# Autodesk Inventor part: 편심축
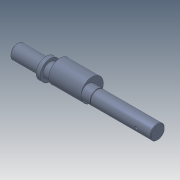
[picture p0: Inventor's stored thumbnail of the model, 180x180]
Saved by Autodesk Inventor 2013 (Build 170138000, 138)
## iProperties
Manager: 한국ATC센터
Company: 한국ATC센터
Created: 2014-10
Part Number: 편심축
Document SubType Name: Modeling
Designer: 한국ATC센터
Density: 7.86 g/cm^3
Material: 강철, 연강
Mass: 1459.35 g
Surface Area: 294.4 cm^2
Volume: 185.668 cm^3
Author: KYOUNG IL JANG
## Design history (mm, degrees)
sketch "스케치1"
  geometry: L1 (-147, 0)-(147, 0); L2 (-147, 0)-(-147, 12.5); L3 (-147, 12.5)-(-47, 12.5); L4 (-47, 12.5)-(-47, 17.5); L5 (-47, 17.5)-(-40, 17.5); L6 (-40, 17.5)-(-40, 12.5); L7 (-40, 12.5)-(41.65, 12.5); L8 (41.65, 12.5)-(41.65, 11.95); L9 (41.65, 11.95)-(43, 11.95); L10 (43, 11.95)-(43, 12.5); L11 (43, 12.5)-(147, 12.5); L12 (147, 12.5)-(147, 0); L13 (114, 12.5)-(114, 9.1); L14 (114, 9.1)-(139, 9.1); L15 (139, 9.1)-(139, 12.5); L16 (122, -12.5)-(124.5, -12.5); L17 (124.5, -12.5)-(122, -10); L18 (122, -10)-(122, -12.5); L19 (-114, 12.5)-(-114, 9.1); L20 (-114, 9.1)-(-139, 9.1); L21 (-139, 9.1)-(-139, 12.5); L22 (-122, -12.5)-(-122, -10); L23 (-122, -10)-(-119.5, -12.5); L24 (-119.5, -12.5)-(-122, -12.5); 2 further points
  constraints: 48 end point, 11 parallel, 8 perpendicular, 5 collinear, 4 point on line, 1 coincident, 1 horizontal, 1 midpoint, 1 vertical
  dimensions: "d0" = 294 distance of L1.start L1.end (derived); "d1" = 25 diameter of L3 L1; "d2" = 35 diameter of L5 L1; "d3" = 100 distance of L2.end L3.end; "d4" = 187 distance between parallel lines of L12 L6; "d6" = 1.35 distance of L8.end L9.end; "d7" = 23.9 diameter of L9 L1; "d8" = 3.4 distance between parallel lines of L14 L11; "d9" = 8 distance between parallel lines of L15 L12; "d10" = 25 distance of L13.end L14.end; "d11" = 25 diameter of L16 L1 (= d1); "d12" = 25 distance from line of L12 L16.start; "d13" = 45 deg angle of L17 L18; "d14" = 5 diameter of L16.end L18; "d27" = 104 distance between parallel lines of L10 L12; "d32" = 7 distance of L4.end L5.end; "d33" = 8 distance between parallel lines of L2 L21; "d34" = 25 distance between parallel lines of L21 L19; "d35" = 3.4 distance between parallel lines of L3 L20; "d36" = 25 distance from line of L22.start L2; "d37" = 5 diameter of L23.end L22
revolve "회전1" stored, may be unused: angle "d15" = 90 deg
revolve "회전2" stored, may be unused: angle "d16" = 90 deg
revolve "회전3" stored, may be unused: angle "d38" = 90 deg
extrude "돌출1" cut sketch "스케치1" stored distance "d17" = 8; taper "d18" = 0 deg
fillet "모깎기1" dims "d19" = 4
node "작업 평면1"
sketch "스케치2"
  geometry: C1 r 12.5 at (0, 0) reference; C2 r 19.5 at (0, 7); 1 further point
  constraints: 1 centre point, 1 tangent, 1 vertical alignment
  dimensions: "d21" = 7 distance of point (0, 0) C2.centre; "d30" = 39 diameter of C2 (derived)
extrude "돌출2" join sketch "스케치2" distance "d22" = 56; taper "d23" = 0 deg
chamfer "모따기1" distance "d24" = 1; stored, may be unused: second distance "d25" = 2, angle "d26" = 45 deg
node "솔리드1"
